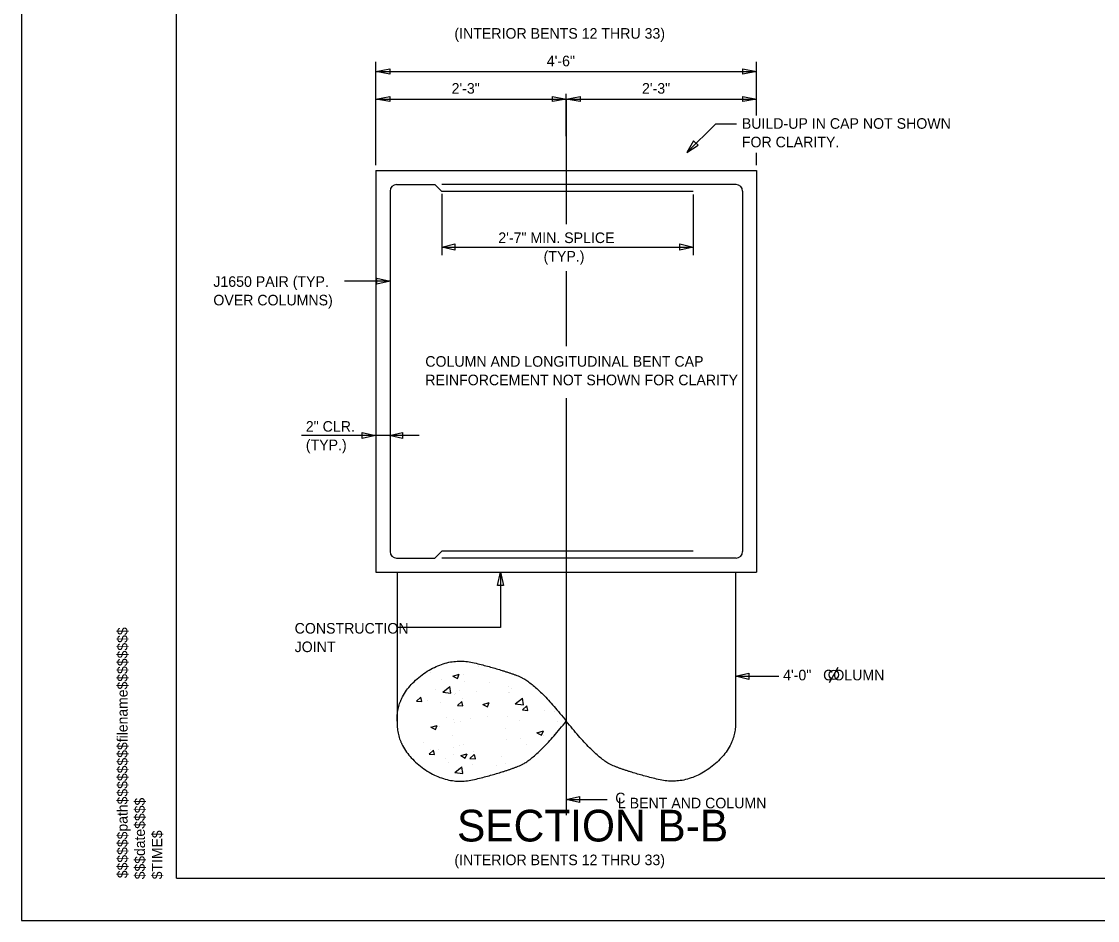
# Model space of a CAD drawing. Extents: x -133.1 to -97, y -1.7 to 20.3.
# Drawn here: x -133.14 to -120.43, y -1.69 to 8.94 of the extents above; entities that cross this region are included whole.
import ezdxf

# ---------------------------------------------------------------- set-up
doc = ezdxf.new("R2010")
doc.units = 0
for name, color, linetype in [('BR_AUTO DIMENSION', 7, 'Continuous'), ('BR_BORDER LINES', 7, 'Continuous'), ('BR_CENTER LINES', 7, 'Continuous'), ('BR_CONCRETE', 7, 'Continuous'), ('BR_REBAR', 7, 'Continuous'), ('BR_TEXT', 7, 'Continuous'), ('Level 31', 7, 'Continuous'), ('RD_SHT_ID', 7, 'Continuous')]:
    doc.layers.add(name, color=color, linetype=linetype)

msp = doc.modelspace()

# ---------------------------------------------------------------- linework, layer by layer
at = {"layer": 'BR_AUTO DIMENSION'}
for p, q in [((-128.953, 7.239), (-128.953, 8.461)), ((-124.453, 7.825), (-124.453, 8.461)), ((-128.953, 8.345), (-124.453, 8.345)), ((-128.953, 8.021), (-126.703, 8.021)), ((-126.703, 7.58), (-126.703, 8.084)), ((-126.703, 8.021), (-124.453, 8.021)), ((-124.453, 7.239), (-124.453, 7.385)), ((-128.175, 6.901), (-128.175, 6.173)), ((-125.203, 6.891), (-125.203, 6.173)), ((-128.175, 6.271), (-125.203, 6.271)), ((-128.786, 5.868), (-129.322, 5.868)), ((-128.441, 4.044), (-129.834, 4.044)), ((-127.479, 2.427), (-127.479, 1.771)), ((-127.479, 1.771), (-128.703, 1.771)), ((-124.703, 1.196), (-124.191, 1.196)), ((-126.703, -0.26), (-126.22, -0.26))]:
    msp.add_line(p, q, dxfattribs=at)
for points in [[(-128.79, 8.314), (-128.953, 8.345), (-128.79, 8.377)], [(-124.615, 8.377), (-124.453, 8.345), (-124.615, 8.314)], [(-128.79, 7.99), (-128.953, 8.021), (-128.79, 8.052)], [(-126.865, 8.052), (-126.703, 8.021), (-126.865, 7.99)], [(-126.54, 7.99), (-126.703, 8.021), (-126.54, 8.052)], [(-124.615, 8.052), (-124.453, 8.021), (-124.615, 7.99)], [(-125.198, 7.527), (-125.28, 7.39), (-125.146, 7.477)], [(-128.019, 6.235), (-128.175, 6.271), (-128.019, 6.307)], [(-125.359, 6.307), (-125.203, 6.271), (-125.359, 6.235)], [(-128.942, 5.904), (-128.786, 5.868), (-128.942, 5.832)], [(-129.115, 4.08), (-128.959, 4.044), (-129.115, 4.008)], [(-128.637, 4.008), (-128.793, 4.044), (-128.637, 4.08)], [(-127.515, 2.271), (-127.479, 2.427), (-127.443, 2.271)], [(-124.547, 1.16), (-124.703, 1.196), (-124.547, 1.232)], [(-126.547, -0.296), (-126.703, -0.26), (-126.547, -0.224)]]:
    msp.add_lwpolyline(points, close=True, dxfattribs=at)
msp.add_lwpolyline([(-125.28, 7.39), (-124.934, 7.727), (-124.69, 7.727)], dxfattribs=at)
at = {"layer": 'BR_BORDER LINES'}
for q in [(-131.308, 19.809), (-97.642, -1.191)]:
    msp.add_line((-131.308, -1.191), q, dxfattribs=at)
at = {"layer": 'BR_CENTER LINES'}
for p, q in [((-126.703, 8.021), (-126.703, 6.543)), ((-126.703, 5.986), (-126.703, 5.098)), ((-126.703, 4.483), (-126.703, -0.445))]:
    msp.add_line(p, q, dxfattribs=at)
at = {"layer": 'BR_CONCRETE'}
for p, q in [((-128.953, 7.177), (-128.953, 2.427)), ((-128.953, 7.177), (-124.453, 7.177)), ((-124.453, 7.177), (-124.453, 2.427)), ((-128.953, 2.427), (-128.703, 2.427)), ((-128.703, 2.427), (-128.703, 0.634)), ((-128.703, 2.427), (-124.703, 2.427)), ((-124.703, 2.427), (-124.453, 2.427)), ((-124.703, 2.427), (-124.703, 0.636)), ((-127.746, 1.312), (-127.746, 1.312)), ((-128.304, 1.243), (-128.304, 1.243)), ((-128.178, 1.162), (-128.178, 1.162)), ((-128.043, 1.198), (-127.967, 1.221)), ((-128.043, 1.198), (-127.989, 1.17)), ((-127.989, 1.17), (-127.967, 1.221)), ((-127.922, 1.215), (-127.922, 1.215)), ((-128.248, 1.042), (-128.248, 1.042)), ((-128.163, 1.008), (-128.079, 1.076)), ((-128.067, 0.997), (-128.079, 1.076)), ((-127.962, 1.024), (-127.962, 1.024)), ((-127.902, 1.136), (-127.902, 1.136)), ((-127.616, 1.117), (-127.616, 1.117)), ((-127.382, 1.072), (-127.382, 1.072)), ((-127.354, 1.053), (-127.354, 1.053)), ((-128.473, 0.902), (-128.421, 0.95)), ((-128.473, 0.902), (-128.409, 0.898)), ((-128.409, 0.898), (-128.421, 0.95)), ((-128.419, 0.914), (-128.419, 0.914)), ((-128.346, 0.905), (-128.346, 0.905)), ((-128.163, 1.008), (-128.067, 0.997)), ((-128.028, 0.984), (-128.028, 0.984)), ((-128.007, 0.988), (-128.007, 0.988)), ((-127.99, 0.85), (-127.938, 0.898)), ((-127.926, 0.846), (-127.938, 0.898)), ((-127.935, 0.938), (-127.935, 0.938)), ((-127.76, 1.011), (-127.76, 1.011)), ((-127.39, 1.005), (-127.39, 1.005)), ((-127.379, 1), (-127.379, 1)), ((-127.305, 0.87), (-127.221, 0.938)), ((-127.209, 0.859), (-127.221, 0.938)), ((-128.191, 0.885), (-128.191, 0.885)), ((-127.99, 0.85), (-127.926, 0.846)), ((-127.689, 0.863), (-127.614, 0.885)), ((-127.689, 0.863), (-127.635, 0.835)), ((-127.635, 0.835), (-127.614, 0.885)), ((-127.305, 0.87), (-127.209, 0.859)), ((-127.221, 0.798), (-127.17, 0.846)), ((-127.221, 0.798), (-127.157, 0.793)), ((-127.157, 0.793), (-127.17, 0.846)), ((-126.959, 0.793), (-126.959, 0.793)), ((-126.842, 0.782), (-126.842, 0.782)), ((-128.115, 0.712), (-128.115, 0.712)), ((-128.041, 0.682), (-128.041, 0.682)), ((-128.024, 0.655), (-128.024, 0.655)), ((-127.948, 0.66), (-127.948, 0.66)), ((-127.829, 0.693), (-127.829, 0.693)), ((-127.636, 0.724), (-127.636, 0.724)), ((-127.392, 0.723), (-127.392, 0.723)), ((-127.257, 0.674), (-127.257, 0.674)), ((-126.802, 0.658), (-126.802, 0.658)), ((-128.303, 0.594), (-128.228, 0.616)), ((-128.303, 0.594), (-128.25, 0.566)), ((-128.25, 0.566), (-128.228, 0.616)), ((-128.204, 0.607), (-128.204, 0.607)), ((-127.427, 0.575), (-127.427, 0.575)), ((-127.049, 0.527), (-126.974, 0.55)), ((-127.049, 0.527), (-126.996, 0.499)), ((-126.996, 0.499), (-126.974, 0.55)), ((-128.391, 0.408), (-128.391, 0.408)), ((-128.052, 0.491), (-128.052, 0.491)), ((-127.961, 0.383), (-127.961, 0.383)), ((-127.917, 0.395), (-127.917, 0.395)), ((-127.405, 0.446), (-127.405, 0.446)), ((-127.241, 0.465), (-127.241, 0.465)), ((-127.17, 0.392), (-127.17, 0.392)), ((-126.973, 0.492), (-126.973, 0.492)), ((-126.855, 0.504), (-126.855, 0.504)), ((-128.324, 0.275), (-128.272, 0.323)), ((-128.324, 0.286), (-128.324, 0.286)), ((-128.324, 0.275), (-128.26, 0.271)), ((-128.306, 0.326), (-128.306, 0.326)), ((-128.26, 0.271), (-128.272, 0.323)), ((-128.217, 0.33), (-128.217, 0.33)), ((-128.038, 0.354), (-128.038, 0.354)), ((-128.038, 0.267), (-128.038, 0.267)), ((-127.949, 0.258), (-127.874, 0.281)), ((-127.949, 0.258), (-127.896, 0.23)), ((-127.896, 0.23), (-127.874, 0.281)), ((-127.841, 0.223), (-127.79, 0.271)), ((-127.795, 0.308), (-127.795, 0.308)), ((-127.777, 0.219), (-127.789, 0.271)), ((-128.134, 0.225), (-128.134, 0.225)), ((-128.098, 0.174), (-128.098, 0.174)), ((-127.841, 0.223), (-127.777, 0.219)), ((-127.812, 0.155), (-127.812, 0.155)), ((-127.523, 0.136), (-127.523, 0.136)), ((-127.466, 0.249), (-127.466, 0.249)), ((-127.418, 0.168), (-127.418, 0.168)), ((-128.021, 0.059), (-127.937, 0.126)), ((-128.021, 0.059), (-127.925, 0.047)), ((-127.974, 0.106), (-127.974, 0.106)), ((-127.925, 0.047), (-127.937, 0.126)), ((-127.914, 0.067), (-127.914, 0.067))]:
    msp.add_line(p, q, dxfattribs=at)
for points in [[(-128.703, 0.666), (-128.712, 0.982), (-128.113, 1.435), (-127.453, 1.272), (-127.064, 1.117), (-126.703, 0.666)], [(-128.703, 0.666), (-128.712, 0.349), (-128.113, -0.104), (-127.453, 0.059), (-127.064, 0.215), (-126.703, 0.666)], [(-124.702, 0.666), (-124.693, 0.349), (-125.292, -0.104), (-125.952, 0.059), (-126.341, 0.215), (-126.703, 0.666)]]:
    msp.add_open_spline(points, degree=2, dxfattribs=at)
at = {"layer": 'BR_REBAR'}
for p, q in [((-128.708, 7.01), (-128.258, 7.01)), ((-128.258, 7.01), (-128.175, 6.927)), ((-124.697, 7.01), (-128.175, 7.01)), ((-128.786, 6.932), (-128.786, 2.671)), ((-125.203, 6.927), (-128.175, 6.927)), ((-124.619, 6.932), (-124.619, 2.671)), ((-128.258, 2.593), (-128.175, 2.677)), ((-125.203, 2.677), (-128.175, 2.677)), ((-128.708, 2.593), (-128.258, 2.593)), ((-124.697, 2.593), (-128.175, 2.593))]:
    msp.add_line(p, q, dxfattribs=at)
for centre, start, end in [((-128.708, 6.932), 90, 180), ((-124.697, 6.932), 360, 90), ((-128.708, 2.671), 180, 270), ((-124.697, 2.671), 270, 360)]:
    msp.add_arc(centre, 0.0781, start, end, dxfattribs=at)
at = {"layer": 'BR_TEXT'}
for p, q in [((-128.175, 6.271), (-128.097, 6.271)), ((-123.593, 1.123), (-123.488, 1.305))]:
    msp.add_line(p, q, dxfattribs=at)
msp.add_circle((-123.541, 1.214), 0.055, dxfattribs=at)
at = {"layer": 'Level 31'}
msp.add_lwpolyline([(-133.141, -1.691), (-97.141, -1.691), (-97.141, 20.309), (-133.141, 20.309)], close=True, dxfattribs=at)

# ---------------------------------------------------------------- texts
at = {"layer": 'BR_AUTO DIMENSION'}
for s, p in [('(INTERIOR BENTS 12 THRU 33)', (-128.025, 8.734)), ('4\'-6"', (-126.933, 8.408)), ('2\'-3"', (-128.058, 8.084)), ('2\'-3"', (-125.808, 8.084)), ('(INTERIOR BENTS 12 THRU 33)', (-128.025, -1.037))]:
    msp.add_text(s, height=0.125, dxfattribs=at).set_placement(p)
at = {"layer": 'BR_TEXT'}
for s, p in [('BUILD-UP IN CAP NOT SHOWN', (-124.628, 7.669)), ('FOR CLARITY.', (-124.628, 7.45)), ('2\'-7" MIN. SPLICE', (-127.506, 6.318)), ('(TYP.)', (-126.971, 6.099)), ('J1650 PAIR (TYP.', (-130.874, 5.8)), ('OVER COLUMNS)', (-130.874, 5.581)), ('COLUMN AND LONGITUDINAL BENT CAP', (-128.369, 4.856)), ('REINFORCEMENT NOT SHOWN FOR CLARITY', (-128.369, 4.637)), ('2" CLR.', (-129.781, 4.088)), ('(TYP.)', (-129.781, 3.869)), ('CONSTRUCTION', (-129.913, 1.701)), ('JOINT', (-129.913, 1.482)), ('4\'-0"   COLUMN', (-124.14, 1.148)), ('C', (-126.124, -0.305)), ('L BENT AND COLUMN', (-126.093, -0.365))]:
    msp.add_text(s, height=0.125, rotation=360, dxfattribs=at).set_placement(p)
msp.add_text('SECTION B-B', height=0.375, dxfattribs=at).set_placement((-127.994, -0.757))
at = {"layer": 'RD_SHT_ID'}
for s, height, p in [('$$$$$$path$$$$$$$$filename$$$$$$$$', 0.12347, (-131.887, -1.191)), ('$$$date$$$$', 0.12347, (-131.682, -1.204)), ('$TIME$', 0.1235, (-131.477, -1.204))]:
    msp.add_text(s, height=height, rotation=90, dxfattribs=at).set_placement(p)

doc.saveas('drawing.dxf')
